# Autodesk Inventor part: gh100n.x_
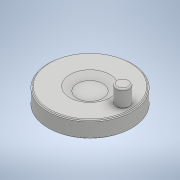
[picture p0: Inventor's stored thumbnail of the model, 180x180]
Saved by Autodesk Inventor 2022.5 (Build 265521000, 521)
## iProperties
Part Number: gh100n.x_
Material: 一般
Document SubType Name: Modeling
Designer: ImaoCorp
Density: 1 g/cm^3
Appearance: 既定
Sending System: SOLIDWORKS 2017-2017317
MC: AMD64
MC_MODEL: Intel64 Family 6 Model 60 Stepping 3, GenuineIntel
OS: Windows_NT
FRU: Parasolid Version 29.0, build 201,  4-17-2017
FORMAT: text
GUISE: transmit
KEY: gh100n
FILE: gh100n.x_t
DATE: Mon Jul 01 17:31:34 2019
Author: ImaoCorp
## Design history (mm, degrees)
feature "Base1"
node "ソリッド1"
